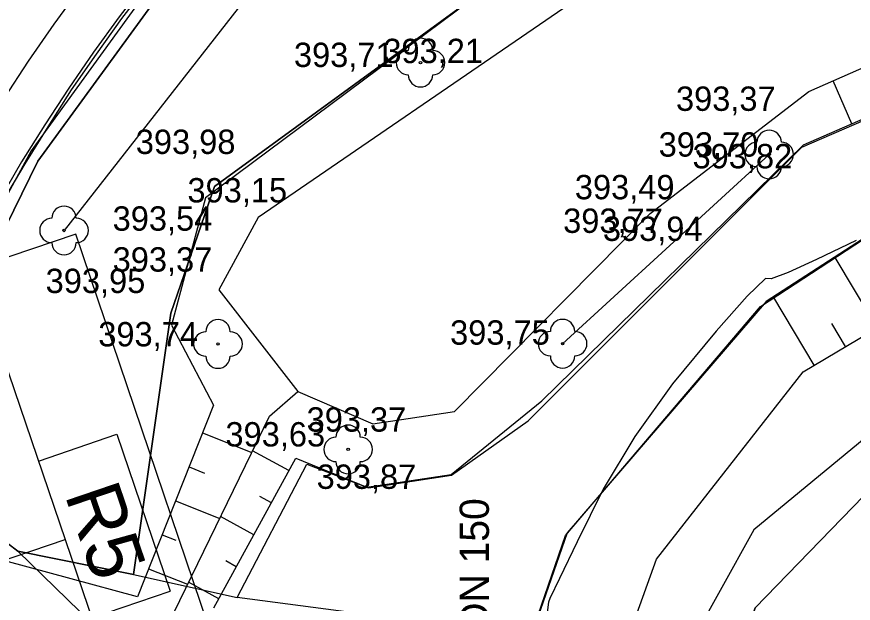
# Model space of a CAD drawing. Extents: x -574342 to -508101, y -1143544 to -1123894.
# Drawn here: x -508530.11 to -508495.78, y -1143176.82 to -1143152.74 of the extents above; entities that cross this region are included whole.
import ezdxf

# ---------------------------------------------------------------- set-up
doc = ezdxf.new("R2010")
doc.units = 0
for name, color, linetype in [('01_PARCELY_NAVRH_PC', 7, 'Continuous'), ('01_PARCELY_NAVRH_VHO', 7, 'Continuous'), ('01_PARCELY_NAVRH_ŽP', 7, 'Continuous'), ('05_VHO_V_NÁDRŽ_STAV', 7, 'Continuous'), ('1000', 7, 'Continuous'), ('15', 7, 'Continuous'), ('21', 7, 'Continuous'), ('37', 7, 'Continuous'), ('51', 7, 'Continuous'), ('54', 7, 'Continuous'), ('55', 7, 'Continuous'), ('60', 7, 'Continuous'), ('61', 7, 'Continuous'), ('Level 255', 7, 'Continuous'), ('SO 101_popis oblouku', 7, 'Continuous'), ('VRST VEDL', 7, 'Continuous')]:
    doc.layers.add(name, color=color, linetype=linetype)

msp = doc.modelspace()

# ---------------------------------------------------------------- linework, layer by layer
msp.add_lwpolyline([(-508548.315, -1143168.642), (-508540.774, -1143190.92), (-508520.151, -1143183.94), (-508527.691, -1143161.661)], close=True)
at = {"layer": '01_PARCELY_NAVRH_PC'}
msp.add_lwpolyline([(-508510.179, -1143116.058), (-508515.95, -1143130.65), (-508519.02, -1143135.54), (-508530.41, -1143150.9), (-508533.66, -1143155.6), (-508539.86, -1143167.27), (-508535.17, -1143170.73), (-508529.25, -1143158.67), (-508513.07, -1143136.47), (-508505.79, -1143121.37), (-508504.685, -1143116.058)], dxfattribs=at)
msp.add_lwpolyline([(-508510.179, -1143116.058), (-508515.95, -1143130.65), (-508519.02, -1143135.54), (-508530.41, -1143150.9), (-508533.66, -1143155.6), (-508539.86, -1143167.27), (-508535.17, -1143170.73), (-508529.25, -1143158.67), (-508513.07, -1143136.47), (-508505.79, -1143121.37), (-508504.685, -1143116.058)], dxfattribs=at)
at = {"layer": '01_PARCELY_NAVRH_VHO'}
msp.add_line((-508525.32, -1143175.64), (-508521.06, -1143176.58), dxfattribs=at)
for points in [[(-508496.906, -1143116.058), (-508498.01, -1143119.91), (-508498.41, -1143129.24), (-508499.11, -1143135.6), (-508503.75, -1143144.67), (-508510.09, -1143151.01), (-508521.99, -1143159.7), (-508523.79, -1143164.91), (-508525.32, -1143175.64), (-508530.07, -1143174.68), (-508516.39, -1143188), (-508504.26, -1143191.1), (-508496.38, -1143198.1)], [(-508446.56, -1143243.12), (-508452.58, -1143244.39), (-508461.81, -1143244.49), (-508467.98, -1143243.62), (-508478.66, -1143222.38), (-508487.9, -1143213.8), (-508496.38, -1143198.1), (-508504.26, -1143191.1), (-508516.39, -1143188), (-508530.07, -1143174.68), (-508539.86, -1143167.27), (-508547.02, -1143163.34), (-508553.27, -1143164.53), (-508559.77, -1143166.35), (-508565.39, -1143163.91), (-508571.39, -1143166.22), (-508578.23, -1143159.53), (-508587.9, -1143163.05), (-508596.45, -1143153.64), (-508600.04, -1143155.89), (-508608.16, -1143150.99), (-508613.1, -1143145.09)], [(-508491.25, -1143159.19), (-508499.36, -1143164.43), (-508507.52, -1143173.92), (-508509.38, -1143179.27), (-508513.26, -1143177.6), (-508521.06, -1143176.58), (-508518.2, -1143171.1), (-508515.68, -1143172.08), (-508512.27, -1143171.56), (-508509.12, -1143169.33), (-508497.89, -1143158.09), (-508486.83, -1143153.3)]]:
    msp.add_lwpolyline(points, dxfattribs=at)
at = {"layer": '01_PARCELY_NAVRH_ŽP'}
msp.add_lwpolyline([(-508504.685, -1143116.058), (-508505.79, -1143121.37), (-508513.07, -1143136.47), (-508529.25, -1143158.67), (-508535.17, -1143170.73), (-508530.07, -1143174.68), (-508525.32, -1143175.64), (-508523.79, -1143164.91), (-508521.99, -1143159.7), (-508510.09, -1143151.01), (-508503.75, -1143144.67), (-508499.11, -1143135.6), (-508498.41, -1143129.24), (-508498.01, -1143119.91), (-508496.906, -1143116.058)], dxfattribs=at)
msp.add_lwpolyline([(-508521.06, -1143176.58), (-508518.2, -1143171.1), (-508515.68, -1143172.08), (-508512.27, -1143171.56), (-508509.12, -1143169.33), (-508497.89, -1143158.09), (-508486.83, -1143153.3), (-508481.34, -1143149.03), (-508479.12, -1143143.52), (-508479.68, -1143136.88), (-508476.26, -1143134.7), (-508463.3, -1143163.03), (-508471.45, -1143157.79), (-508480.5, -1143156.13), (-508491.25, -1143159.19), (-508499.36, -1143164.43), (-508507.52, -1143173.92), (-508509.38, -1143179.27), (-508513.26, -1143177.6)], close=True, dxfattribs=at)
at = {"layer": '05_VHO_V_NÁDRŽ_STAV'}
msp.add_lwpolyline([(-508460.83, -1143194.159), (-508460.83, -1143190.06), (-508464.4, -1143180.91), (-508469.37, -1143169.34), (-508471.53, -1143166.68), (-508474.42, -1143165.09), (-508480.95, -1143165.04), (-508489.11, -1143168.14), (-508494.91, -1143171.96), (-508499.81, -1143177.01), (-508501.3, -1143181.37), (-508501.49, -1143182.82), (-508501.26, -1143185.56), (-508499.61, -1143188.4), (-508492.34, -1143191.56), (-508489.27, -1143194.04)], dxfattribs=at)
at = {"layer": '1000'}
for points in [[(-508524.82, -1143151.31), (-508525.906, -1143152.739), (-508526.958, -1143154.193), (-508527.976, -1143155.671), (-508528.96, -1143157.172), (-508529.91, -1143158.695), (-508530.824, -1143160.24)], [(-508524.724, -1143151.384), (-508525.806, -1143152.813), (-508526.855, -1143154.266), (-508527.871, -1143155.742), (-508528.834, -1143157.253), (-508529.785, -1143158.771), (-508530.692, -1143160.316)]]:
    msp.add_lwpolyline(points, dxfattribs=at)
at = {"layer": '21'}
msp.add_lwpolyline([(-508527.512, -1143151.548), (-508528.592, -1143153.04), (-508529.636, -1143154.555), (-508530.645, -1143156.095)], dxfattribs=at)
at = {"layer": '37'}
msp.add_lwpolyline([(-508508.39, -1143126.78), (-508512.62, -1143134.91), (-508529.52, -1143158.24), (-508537.33, -1143172.61), (-508540.68, -1143183.59)], dxfattribs=at)
msp.add_lwpolyline([(-508508.39, -1143126.78), (-508512.62, -1143134.91), (-508529.52, -1143158.24), (-508537.33, -1143172.61), (-508540.68, -1143183.59)], dxfattribs=at)
at = {"layer": '51'}
for points in [[(-508493.571, -1143116.058), (-508495.44, -1143120.19), (-508495.95, -1143129.08), (-508496.26, -1143135.35), (-508498.94, -1143141.93), (-508503.68, -1143148.5), (-508507.66, -1143152.38), (-508520.2, -1143160.98), (-508521.82, -1143163.95), (-508518.57, -1143168.12), (-508515.5, -1143169.45), (-508512.14, -1143168.95), (-508504.12, -1143160.81), (-508497.6, -1143155.8), (-508487.25, -1143151.23), (-508483.67, -1143147.96), (-508481.24, -1143143.89), (-508482.47, -1143135.96), (-508484.03, -1143128.35), (-508484.73, -1143123.98), (-508486.94, -1143118.54), (-508489.496, -1143116.058)], [(-508493.571, -1143116.058), (-508495.44, -1143120.19), (-508495.95, -1143129.08), (-508496.26, -1143135.35), (-508498.94, -1143141.93), (-508503.68, -1143148.5), (-508507.66, -1143152.38), (-508520.2, -1143160.98), (-508521.82, -1143163.95), (-508518.57, -1143168.12), (-508515.5, -1143169.45), (-508512.14, -1143168.95), (-508504.12, -1143160.81), (-508497.6, -1143155.8), (-508487.25, -1143151.23), (-508483.67, -1143147.96), (-508481.24, -1143143.89), (-508482.47, -1143135.96), (-508484.03, -1143128.35), (-508484.73, -1143123.98), (-508486.94, -1143118.54), (-508489.496, -1143116.058)], [(-508501.3, -1143181.37), (-508499.81, -1143177.01), (-508494.91, -1143171.96), (-508489.11, -1143168.14), (-508480.95, -1143165.04), (-508474.42, -1143165.09), (-508471.53, -1143166.68), (-508469.37, -1143169.34), (-508464.4, -1143180.91), (-508460.83, -1143190.06), (-508460.83, -1143200.16)], [(-508501.3, -1143181.37), (-508499.81, -1143177.01), (-508494.91, -1143171.96), (-508489.11, -1143168.14), (-508480.95, -1143165.04), (-508474.42, -1143165.09), (-508471.53, -1143166.68), (-508469.37, -1143169.34), (-508464.4, -1143180.91), (-508460.83, -1143190.06), (-508460.83, -1143200.16)]]:
    msp.add_lwpolyline(points, dxfattribs=at)
at = {"layer": '54'}
for centre in [(-508513.54, -1143154.62), (-508499.23, -1143158.39), (-508528.17, -1143161.51), (-508521.85, -1143166.17), (-508507.71, -1143166.16), (-508516.51, -1143170.5)]:
    msp.add_circle(centre, 0.05, dxfattribs=at)
for centre, start, end in [((-508513.54, -1143154.12), 0, 180), ((-508514.04, -1143154.62), 90, 270), ((-508513.04, -1143154.62), 270, 90), ((-508513.54, -1143155.12), 180, 0), ((-508499.23, -1143157.89), 0, 180), ((-508499.73, -1143158.39), 90, 270), ((-508498.73, -1143158.39), 270, 90), ((-508499.23, -1143158.89), 180, 0), ((-508528.17, -1143161.01), 0, 180), ((-508528.67, -1143161.51), 90, 270), ((-508527.67, -1143161.51), 270, 90), ((-508528.17, -1143162.01), 180, 0), ((-508521.85, -1143165.67), 0, 180), ((-508507.71, -1143165.66), 0, 180), ((-508522.35, -1143166.17), 90, 270), ((-508521.35, -1143166.17), 270, 90), ((-508508.21, -1143166.16), 90, 270), ((-508507.21, -1143166.16), 270, 90), ((-508521.85, -1143166.67), 180, 0), ((-508507.71, -1143166.66), 180, 0), ((-508516.51, -1143170), 0, 180), ((-508517.01, -1143170.5), 90, 270), ((-508516.01, -1143170.5), 270, 90), ((-508516.51, -1143171), 180, 0)]:
    msp.add_arc(centre, 0.5, start, end, dxfattribs=at)
at = {"layer": '55'}
msp.add_line((-508499.23, -1143158.39), (-508507.71, -1143166.16), dxfattribs=at)
msp.add_line((-508499.23, -1143158.39), (-508507.71, -1143166.16), dxfattribs=at)
msp.add_lwpolyline([(-508501.781, -1143116.058), (-508504.08, -1143125.77), (-508509.69, -1143137.89), (-508528.17, -1143161.51)], dxfattribs=at)
msp.add_lwpolyline([(-508501.781, -1143116.058), (-508504.08, -1143125.77), (-508509.69, -1143137.89), (-508528.17, -1143161.51)], dxfattribs=at)
at = {"layer": '60'}
for points in [[(-508496.861, -1143116.058), (-508498.11, -1143120.78), (-508498.36, -1143129.97), (-508499.28, -1143136.1), (-508504.42, -1143145.69), (-508510.09, -1143151.01), (-508522.36, -1143160.17), (-508523.76, -1143165.4), (-508522.03, -1143168.68), (-508525.16, -1143176.55)], [(-508496.861, -1143116.058), (-508498.11, -1143120.78), (-508498.36, -1143129.97), (-508499.28, -1143136.1), (-508504.42, -1143145.69), (-508510.09, -1143151.01), (-508522.36, -1143160.17), (-508523.76, -1143165.4), (-508522.03, -1143168.68), (-508525.16, -1143176.55)], [(-508496.861, -1143116.058), (-508498.11, -1143120.78), (-508498.36, -1143129.97), (-508499.28, -1143136.1), (-508504.42, -1143145.69), (-508510.09, -1143151.01), (-508522.36, -1143160.17), (-508523.76, -1143165.4), (-508522.03, -1143168.68), (-508525.16, -1143176.55)], [(-508496.861, -1143116.058), (-508498.11, -1143120.78), (-508498.36, -1143129.97), (-508499.28, -1143136.1), (-508504.42, -1143145.69), (-508510.09, -1143151.01), (-508522.36, -1143160.17), (-508523.76, -1143165.4), (-508522.03, -1143168.68), (-508525.16, -1143176.55)], [(-508515.74, -1143172.05), (-508512.28, -1143171.53), (-508508.56, -1143168.5), (-508497.82, -1143157.99), (-508486.77, -1143153.18), (-508481.27, -1143148.82), (-508479.19, -1143143.42), (-508479.72, -1143136.69), (-508476.24, -1143134.48), (-508476.7, -1143133.48), (-508480.34, -1143134.37), (-508481.13, -1143128.49), (-508479.36, -1143127.67), (-508479.81, -1143126.52), (-508482.03, -1143126.91), (-508483.98, -1143117.49), (-508484.986, -1143116.058)], [(-508515.74, -1143172.05), (-508512.28, -1143171.53), (-508508.56, -1143168.5), (-508497.82, -1143157.99), (-508486.77, -1143153.18), (-508481.27, -1143148.82), (-508479.19, -1143143.42), (-508479.72, -1143136.69), (-508476.24, -1143134.48), (-508476.7, -1143133.48), (-508480.34, -1143134.37), (-508481.13, -1143128.49), (-508479.36, -1143127.67), (-508479.81, -1143126.52), (-508482.03, -1143126.91), (-508483.98, -1143117.49), (-508484.986, -1143116.058)], [(-508509.56, -1143179.75), (-508507.59, -1143174.03), (-508499.59, -1143164.63), (-508491.49, -1143159.34), (-508480.74, -1143156.18), (-508471.54, -1143157.78), (-508463.5, -1143162.91), (-508457.05, -1143173.57)], [(-508509.56, -1143179.75), (-508507.59, -1143174.03), (-508499.59, -1143164.63), (-508491.49, -1143159.34), (-508480.74, -1143156.18), (-508471.54, -1143157.78), (-508463.5, -1143162.91), (-508457.05, -1143173.57)], [(-508506.58, -1143184.83), (-508505.59, -1143179.84), (-508503.86, -1143175), (-508497.84, -1143167.31), (-508489.61, -1143162.43), (-508480.59, -1143159.39), (-508472.18, -1143160.07), (-508465.72, -1143164.54), (-508460.82, -1143174.63)], [(-508506.58, -1143184.83), (-508505.59, -1143179.84), (-508503.86, -1143175), (-508497.84, -1143167.31), (-508489.61, -1143162.43), (-508480.59, -1143159.39), (-508472.18, -1143160.07), (-508465.72, -1143164.54), (-508460.82, -1143174.63)], [(-508455.56, -1143236.37), (-508453.06, -1143233.89), (-508451.99, -1143229.27), (-508454.51, -1143221.16), (-508458.09, -1143209.77), (-508458.76, -1143200.63), (-508458.93, -1143189.23), (-508462.08, -1143179.93), (-508467.63, -1143168.34), (-508471.31, -1143163.81), (-508477.14, -1143162.33), (-508483.91, -1143163.18), (-508491.81, -1143167.17), (-508499.86, -1143173.8), (-508502.62, -1143178.78)], [(-508455.56, -1143236.37), (-508453.06, -1143233.89), (-508451.99, -1143229.27), (-508454.51, -1143221.16), (-508458.09, -1143209.77), (-508458.76, -1143200.63), (-508458.93, -1143189.23), (-508462.08, -1143179.93), (-508467.63, -1143168.34), (-508471.31, -1143163.81), (-508477.14, -1143162.33), (-508483.91, -1143163.18), (-508491.81, -1143167.17), (-508499.86, -1143173.8), (-508502.62, -1143178.78)], [(-508524.5, -1143179.18), (-508523.67, -1143177.21), (-508519.74, -1143169.14), (-508518.57, -1143168.12)], [(-508524.5, -1143179.18), (-508523.67, -1143177.21), (-508519.74, -1143169.14), (-508518.57, -1143168.12)], [(-508522.02, -1143177), (-508518.66, -1143170.86), (-508515.74, -1143172.05)], [(-508522.02, -1143177), (-508518.66, -1143170.86), (-508515.74, -1143172.05)], [(-508525.16, -1143176.55), (-508530.6, -1143175.07), (-508532.55, -1143176.28), (-508533.83, -1143178.28), (-508532.4, -1143181.41), (-508525.65, -1143187.42), (-508523.14, -1143191), (-508516.45, -1143194.78), (-508517.33, -1143196.24), (-508514.08, -1143199.23), (-508507.94, -1143200.06), (-508504.93, -1143199.98), (-508503.26, -1143200.81), (-508496.6, -1143211.46), (-508497.83, -1143216.41), (-508496.7, -1143219.56), (-508489.97, -1143220.34), (-508484.25, -1143225.74), (-508480.17, -1143231.74), (-508475.87, -1143242.05), (-508473.98, -1143249.93), (-508471.29, -1143252.95)], [(-508525.16, -1143176.55), (-508530.6, -1143175.07), (-508532.55, -1143176.28), (-508533.83, -1143178.28), (-508532.4, -1143181.41), (-508525.65, -1143187.42), (-508523.14, -1143191), (-508516.45, -1143194.78), (-508517.33, -1143196.24), (-508514.08, -1143199.23), (-508507.94, -1143200.06), (-508504.93, -1143199.98), (-508503.26, -1143200.81), (-508496.6, -1143211.46), (-508497.83, -1143216.41), (-508496.7, -1143219.56), (-508489.97, -1143220.34), (-508484.25, -1143225.74), (-508480.17, -1143231.74), (-508475.87, -1143242.05), (-508473.98, -1143249.93), (-508471.29, -1143252.95)]]:
    msp.add_lwpolyline(points, dxfattribs=at)
at = {"layer": '61'}
for p, q in [((-508495.841, -1143157.129), (-508496.61, -1143155.363)), ((-508495.841, -1143157.129), (-508496.61, -1143155.363)), ((-508494.806, -1143165.511), (-508496.518, -1143162.624)), ((-508494.806, -1143165.511), (-508496.518, -1143162.624)), ((-508497.387, -1143167.041), (-508499.032, -1143164.266)), ((-508497.387, -1143167.041), (-508499.032, -1143164.266)), ((-508496.097, -1143166.276), (-508496.656, -1143165.333)), ((-508496.097, -1143166.276), (-508496.656, -1143165.333)), ((-508522.485, -1143169.823), (-508520.464, -1143170.627)), ((-508522.485, -1143169.823), (-508520.464, -1143170.627)), ((-508518.94, -1143171.371), (-508520.429, -1143170.556)), ((-508518.94, -1143171.371), (-508520.429, -1143170.556)), ((-508523.039, -1143171.217), (-508522.401, -1143171.471)), ((-508523.039, -1143171.217), (-508522.401, -1143171.471)), ((-508523.593, -1143172.611), (-508521.781, -1143173.331)), ((-508523.593, -1143172.611), (-508521.781, -1143173.331)), ((-508519.66, -1143172.687), (-508520.135, -1143172.427)), ((-508519.66, -1143172.687), (-508520.135, -1143172.427)), ((-508520.38, -1143174.003), (-508521.744, -1143173.256)), ((-508520.38, -1143174.003), (-508521.744, -1143173.256)), ((-508524.148, -1143174.004), (-508523.579, -1143174.231)), ((-508524.148, -1143174.004), (-508523.579, -1143174.231)), ((-508524.702, -1143175.398), (-508523.098, -1143176.036)), ((-508524.702, -1143175.398), (-508523.098, -1143176.036)), ((-508521.1, -1143175.319), (-508521.533, -1143175.081)), ((-508521.1, -1143175.319), (-508521.533, -1143175.081)), ((-508521.82, -1143176.634), (-508523.059, -1143175.956)), ((-508521.82, -1143176.634), (-508523.059, -1143175.956))]:
    msp.add_line(p, q, dxfattribs=at)
at = {"layer": 'SO 101_popis oblouku'}
for p, q in [((-508531.782, -1143163.468), (-508524.47, -1143184.922)), ((-508529.223, -1143170.977), (-508526.005, -1143169.88)), ((-508526.005, -1143169.88), (-508523.811, -1143176.316)), ((-508544.218, -1143179.679), (-508528.126, -1143174.195)), ((-508527.03, -1143177.413), (-508523.811, -1143176.316))]:
    msp.add_line(p, q, dxfattribs=at)
at = {"layer": 'VRST VEDL'}
msp.add_lwpolyline([(-508495.654, -1143161.919), (-508497.284, -1143162.707), (-508498.448, -1143163.232), (-508499.146, -1143163.492), (-508499.379, -1143163.489), (-508500.132, -1143164.206), (-508501.405, -1143165.643), (-508503.198, -1143167.802), (-508504.745, -1143169.964), (-508506.048, -1143172.13), (-508507.106, -1143174.3), (-508507.833, -1143175.797), (-508508.228, -1143176.623), (-508508.292, -1143176.777), (-508508.347, -1143177.193)], dxfattribs=at)

# ---------------------------------------------------------------- texts
at = {"layer": '15'}
msp.add_text('DN 150', height=1.2, rotation=90.0117, dxfattribs=at).set_placement((-508510.731, -1143177.945))
msp.add_text('DN 150', height=1.2, rotation=90.0117, dxfattribs=at).set_placement((-508510.731, -1143177.945))
at = {"layer": 'Level 255'}
for s, p in [('393,21', (-508515.065, -1143154.64)), ('393,71', (-508518.735, -1143154.8)), ('393,37', (-508503.055, -1143156.6)), ('393,98', (-508525.225, -1143158.37)), ('393,70', (-508503.765, -1143158.48)), ('393,82', (-508502.375, -1143158.96)), ('393,49', (-508507.205, -1143160.23)), ('393,15', (-508523.105, -1143160.36)), ('393,54', (-508526.175, -1143161.52)), ('393,77', (-508507.685, -1143161.61)), ('393,94', (-508506.055, -1143161.94)), ('393,37', (-508526.175, -1143163.2)), ('393,95', (-508528.925, -1143164.08)), ('393,74', (-508526.765, -1143166.27)), ('393,75', (-508512.325, -1143166.2)), ('393,37', (-508518.215, -1143169.77)), ('393,63', (-508521.545, -1143170.38)), ('393,87', (-508517.805, -1143172.12))]:
    msp.add_text(s, height=1, dxfattribs=at).set_placement(p)
at = {"layer": 'SO 101_popis oblouku'}
msp.add_text('R5', height=2.2667, rotation=288.8145, dxfattribs=at).set_placement((-508528.154, -1143172.357))

doc.saveas('drawing.dxf')
